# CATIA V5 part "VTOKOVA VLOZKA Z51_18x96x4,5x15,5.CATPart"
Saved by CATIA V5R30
Part number: VTOKOVA VLOZKA
Bounding box of the stored display mesh (mm): x 0 to 98, y -19 to 18.99, z -19 to 19
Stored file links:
  C:\Users\ondra\Desktop\PŘÍLOHA P III\CATIA\VTOKOVA VLOZKA Z51_18x96x4,5x15,5.CATPart
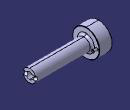
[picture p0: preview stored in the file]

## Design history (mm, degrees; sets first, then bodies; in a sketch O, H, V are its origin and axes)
Set1
  DatumSurface1 to DatumSurface23 "Z51/18x9"
  DatumSurface24 to DatumSurface31 "Z25/4x12"
  Join1: Elements (DatumSurface1; DatumSurface2; DatumSurface3; DatumSurface4; DatumSurface5; DatumSurface6; DatumSurface7; DatumSurface8; DatumSurface9; DatumSurface10; DatumSurface11; DatumSurface12; DatumSurface13; DatumSurface14; DatumSurface15; DatumSurface16; DatumSurface17; DatumSurface18; DatumSurface19; DatumSurface20; DatumSurface21; DatumSurface22; DatumSurface23)
  Join2: Elements (DatumSurface24; DatumSurface25; DatumSurface26; DatumSurface27; DatumSurface28; DatumSurface29; DatumSurface30; DatumSurface31)
Body1 (main body)
  CloseSurface1 "vlozka": CloseElement Join1
  CloseSurface2 "kolik": CloseElement Join2
  Plane1: type Offset, RefPlane yz-plane, Offset 114
  Plane2: stored without definition
  Sketch1 on Plane1, origin (114, 0, 0), H (0, 1, 0), V (0, 0, 1)
    projected arc E1 centre (0, 0) radius 9 from (0, -9) to (0, 9) ccw from edge [face of CloseSurface1 | face of CloseSurface1]
    projected arc E2 centre (0, 0) radius 9 from (0, 9) to (0, -9) ccw from edge [face of CloseSurface1 | face of CloseSurface1]
  Pocket1: profile Sketch1, direction (-1, 0, 0), up to Plane2
  Sketch2, origin (98, 0, 0), H (1, 0, 0), V (0, 0, -1), geometry linked from another document
  Pocket2: profile Sketch2, direction (0, -1, 0), through (limit type 6), opposite side through (limit type 6)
